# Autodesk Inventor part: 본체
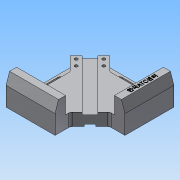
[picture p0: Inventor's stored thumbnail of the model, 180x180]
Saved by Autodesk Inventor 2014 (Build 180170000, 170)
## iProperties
Created: 2020-05
Part Number: 본체
Material: 알루미늄 6061
Document SubType Name: Modeling
Designer: net
Mass: 579.63 g
Surface Area: 410.145 cm^2
Volume: 213.885 cm^3
Density: 2.71 g/cm^3
Appearance: 알루미늄 - 평지
Author: net
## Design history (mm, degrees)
sketch "스케치1"
  geometry: L1 (-60, 60)-(60, 60); L2 (60, 60)-(60, -60); L3 (60, -60)-(-60, -60); L4 (-60, -60)-(-60, 60); L5 (-60, 60)-(60, -60); L6 (60, 60)-(-60, -60); L7 (60, -45)-(-60, -45); L8 (45, 60)-(45, -60); L9 (60, -10)-(38.284, -10); L10 (38.284, -10)-(10, -38.284); L11 (10, -38.284)-(10, -60); L12 (-60, -45)-(-40, -30); L13 (-40, -30)-(-40, 11.716); L14 (-40, 11.716)-(-60, 31.716); L15 (30, 40)-(-11.716, 40); L16 (-11.716, 40)-(-31.716, 60); L17 (-60, 31.716)-(-31.716, 60); L18 (30, 40)-(45, 60); L19 (41.25, 55)-(-26.716, 55); L20 (-55, -41.25)-(-55, 26.716); L21 (22, 48)-(-6, 48); L22 (22, 52)-(-6, 52); L23 (-6, 44)-(22, 44); L24 (-48, -22)-(-48, 6); L25 (-44, -22)-(-44, 6); L26 (-52, 6)-(-52, -22); A1 r 4 centre (22, 48) between (22, 44) and (22, 52); A2 r 4 centre (-6, 48) between (-6, 52) and (-6, 44); A3 r 4 centre (-48, -22) between (-52, -22) and (-44, -22); A4 r 4 centre (-48, 6) between (-44, 6) and (-52, 6); 3 further points
  constraints: 56 end point, 12 point on line, 10 parallel, 9 perpendicular, 8 point on circle, 8 tangent, 4 centre point, 4 midpoint, 1 horizontal
  dimensions: "d16" = 120 distance of L2.end L3.end; "d17" = 120 distance of L1.end L2.end; "d18" = 15 distance between parallel lines of L3 L7; "d19" = 15 distance between parallel lines of L2 L8; "d20" = 50 distance between parallel lines of L3 L9; "d21" = 50 distance between parallel lines of L2 L11; "d23" = 40 distance of L9.end L10.end; "d26" = 15 distance between parallel lines of L20 L13; "d27" = 15 distance between parallel lines of L19 L15; "d28" = 5 distance between parallel lines of L1 L19; "d29" = 5 distance between parallel lines of L4 L20; "d30" = 30 horizontal distance of L1.end L15.start; "d32" = 30 vertical distance of L12.end L3.end; "d33" = 28 distance of L21.end L21.start; "d34" = 8 distance between parallel lines of L22 L23; "d35" = 12 distance from line of L1 L21.start; "d36" = 38 distance from line of L21.start L2; "d37" = 8 diameter of A4; "d38" = 28 distance of L24.end L24.start; "d39" = 38 distance from line of L24.start L3; "d40" = 12 distance from line of L4 L24.start; "d74" = 40 distance of L14.end L16.end
extrude "돌출1" new body sketch "스케치1" distance "d41" = 18; taper "d42" = 0 deg
extrude "돌출2" join sketch "스케치1" distance "d43" = 8; taper "d44" = 0 deg
extrude "돌출3" cut sketch "스케치1" distance "d45" = 18; taper "d46" = 0 deg
extrude "돌출4" join sketch "스케치1" distance "d47" = 42; taper "d48" = 0 deg
extrude "돌출5" cut sketch "스케치1" distance "d49" = 42; taper "d50" = 0 deg
sketch "스케치2"
  geometry: L1 (-40, 0)-(0, 0) reference; L2 (-40, 18)-(0, 18) reference; L3 (-28, 21.5)-(-12, 21.5); L4 (-12, 21.5)-(-12, 14.5); L5 (-12, 14.5)-(-28, 14.5); L6 (-28, 14.5)-(-28, 21.5); L7 (-26, 3)-(-14, 3); L8 (-14, 3)-(-14, -3); L9 (-14, -3)-(-26, -3); L10 (-26, -3)-(-26, 3); 5 further points
  constraints: 16 end point, 4 midpoint, 4 parallel, 2 horizontal, 2 perpendicular, 2 vertical alignment
  dimensions: "d51" = 16 distance of L3.start L3.end; "d52" = 12 distance of L8.end L9.end; "d54" = 3.5 distance between parallel lines of L2 L5; "d56" = 3 distance between parallel lines of L7 L1; "d57" = 7 distance between parallel lines of L5 L3; "d58" = 6 distance between parallel lines of L7 L9
extrude "돌출6" cut sketch "스케치2" stored distance "d59" = 0; taper "d60" = 0 deg
sketch "스케치3"
  geometry: L1 (15, -42)-(0, -42) reference; L2 (15, 0)-(15, -42) reference; L3 (15, -42)-(10, -42); L4 (15, -42)-(15, -27); L5 (15, -27)-(10, -42); 1 further point
  constraints: 6 end point, 2 point on line
  dimensions: "d62" = 5 distance of L1.start L3.end; "d63" = 15 distance of L1.start L4.end
extrude "돌출7" cut sketch "스케치3" stored distance "d64" = 0; taper "d65" = 0 deg
sketch "스케치4"
  geometry: L1 (0, 0)-(42, 0) reference; L2 (42, 15)-(42, 0) reference; L3 (42, 0)-(42, 5); L4 (42, 0)-(27, 0); L5 (27, 0)-(42, 5); 1 further point
  constraints: 6 end point, 2 point on line
  dimensions: "d66" = 5 distance of L1.end L3.end; "d67" = 15 distance of L1.end L4.end
extrude "돌출8" cut sketch "스케치4" stored distance "d68" = 0; taper "d69" = 0 deg
sketch "스케치7"
  geometry: L1 (31.716, 60)-(41.615, 50.101) reference; L2 (26.716, 55)-(31.716, 60) reference; L3 (50.101, 41.615)-(60, 31.716) reference; L4 (50.101, 41.615)-(-19.899, -28.385) reference; L5 (60, 31.716)-(55, 26.716) reference; 5 further points
  dimensions: "d79" = 6 distance from line of point (31.716, 51.515) L1; "d80" = 6 distance from line of L3 point (51.515, 31.716); "d81" = 6 distance from line of point (31.716, 51.515) L2; "d83" = 18 distance from line of point (23.23, 43.029) L1; "d84" = 18 distance from line of point (43.029, 23.23) L3; "d85" = 6 distance from line of point (23.23, 43.029) L2; "d87" = 6 distance from line of point (51.515, 31.716) L5; "d88" = 6 distance from line of point (43.029, 23.23) L5
hole "구멍1" sketch "스케치7" at (31.716, 51.515), (23.23, 43.029), (51.515, 31.716), (43.029, 23.23) diameter "d89" = 4.5; stored, may be unused: countersink angle "d93" = 90 deg, drill point angle "d95" = 0 deg; dims "d90" = 6, "d91" = 8, "d92" = 10, "d94" = 18
sketch "스케치8"
  geometry: L1 (45, 60)-(45, -10) reference; L2 (45, -10)-(55, -10) reference; 2 further points
  constraints: 1 other
  dimensions: "d96" = 5 distance from line of point (50, 25) L1; "d97" = 35 distance from line of point (50, 25) L2
feature "엠보싱1" sketch "스케치8" dims "d98" = 0.5, "d99" = 0
fillet "모깎기1" dims "d100" = 5
node "솔리드1"
